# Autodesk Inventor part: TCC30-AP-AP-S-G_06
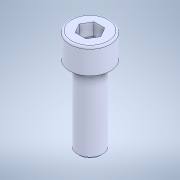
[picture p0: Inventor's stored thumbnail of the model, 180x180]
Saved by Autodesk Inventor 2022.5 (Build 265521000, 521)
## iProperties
Created: 2023-09
Part Number: TCC30-AP-AP-S-G_06
Material: 一般
Document SubType Name: Modeling
Designer: ImaoCorp
Density: 1 g/cm^3
Appearance: 既定
Author: ImaoCorp
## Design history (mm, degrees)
feature "TCC30-AP-AP-S-G_06"
node "ソリッド1"
